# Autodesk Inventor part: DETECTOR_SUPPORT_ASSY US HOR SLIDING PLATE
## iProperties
Shininess: 64.0
Length Units: 11272
Angle Units: 11279
Time Units: 11290
Mass Units: 11286
Length Display Precision: 3
Angle Display Precision: 2
Compacted: True
Part Number: DETECTOR_SUPPORT_ASSY US HOR SLIDING PLATE
Document SubType Name: Modeling
Created: 2004-08
Designer: John Blackburn
Material: MILD_STEEL
Manufacturer: Standard
Standards Organization: Custom
Density: 0.0
Volumn: 0.0
Area: 0.0
PropertySet Name: Model Information
Control State: 0
Master: False
Checked Out: False
Author: John Blackburn
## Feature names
1. ExtrusionMidplane1
2. ExtrusionThru1
